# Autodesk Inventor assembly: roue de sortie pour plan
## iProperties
Shininess: 64.0
Length Units: 11269
Angle Units: 11279
Time Units: 11290
Mass Units: 11283
Length Display Precision: 3
Angle Display Precision: 2
Compacted: True
Created: 2004-09
Part Number: roue de sortie pour plan
Document SubType Name: Assembly
Designer: Administrateur
Density: 0.0
Volumn: 0.0
Area: 0.0
PropertySet Name: Model Information
Control State: 0
Master: False
Checked Out: False
Author: Administrateur
